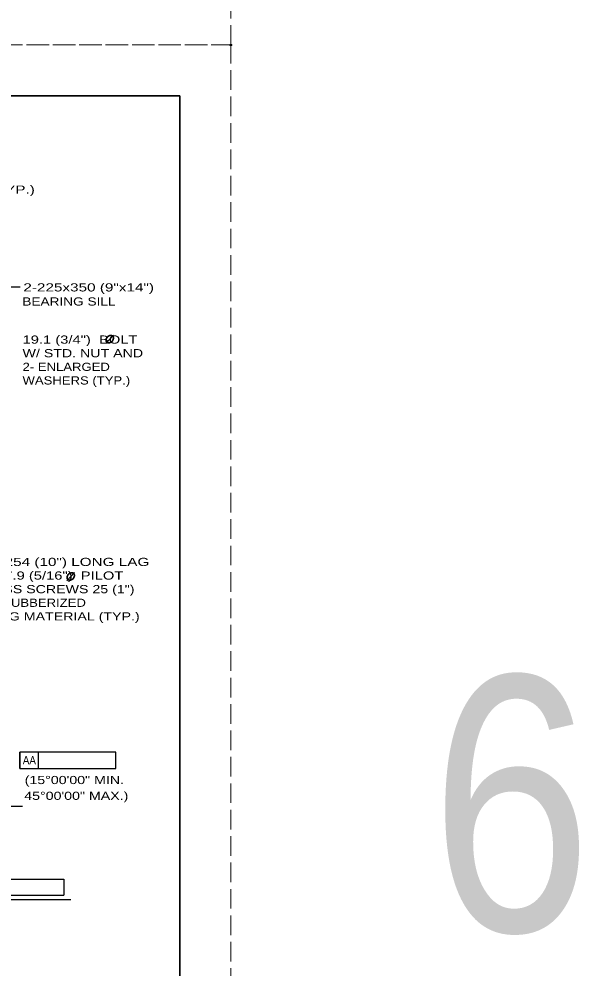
# Model space of a CAD drawing. Extents: x -6.4 to 73.1, y -66 to 0.
# Drawn here: x 64.89 to 73.12, y -57.56 to -43.62 of the extents above; entities that cross this region are included whole.
import ezdxf
from ezdxf.enums import TextEntityAlignment as Align

# ---------------------------------------------------------------- set-up
doc = ezdxf.new("R2010")
doc.units = 0
doc.header["$LTSCALE"] = 0.048
doc.header["$PDMODE"] = 32
doc.header["$PDSIZE"] = 0.024
doc.linetypes.add('LONG_DASHED', pattern=[7.5, 6, -1.5])
for name, color, linetype, lineweight in [('1', 7, 'Continuous', 13), ('4', 7, 'Continuous', 25), ('5', 7, 'Continuous', 25), ('63', 7, 'LONG_DASHED', 13)]:
    doc.layers.add(name, color=color, linetype=linetype, lineweight=lineweight)
doc.layers.add('53', color=7, linetype='Continuous')
doc.layers.add('62', color=7, linetype='Continuous')

msp = doc.modelspace()

# ---------------------------------------------------------------- linework, layer by layer
at = {"layer": '1', "lineweight": 35}
msp.add_lwpolyline([(35.75, -65.25), (67.25, -65.25), (67.25, -44.75), (35.75, -44.75)], close=True, dxfattribs=at)
at = {"layer": '4'}
for p, q in [((64.73475, -47.55442), (64.9015, -47.55442)), ((64.89708, -54.391), (64.89708, -54.62717)), ((66.30908, -54.391), (64.89708, -54.391)), ((64.89708, -54.62717), (64.89708, -54.391)), ((65.17092, -54.62717), (65.17092, -54.391)), ((66.30908, -54.62717), (66.30908, -54.391)), ((64.89708, -54.62717), (66.30908, -54.62717)), ((63.36142, -55.18092), (64.94, -55.18092)), ((63.97042, -56.25308), (65.54517, -56.25317)), ((65.54517, -56.25317), (65.54517, -56.48933)), ((63.45308, -56.55433), (65.65033, -56.55433))]:
    msp.add_line(p, q, dxfattribs=at)
msp.add_lwpolyline([(63.97042, -56.25308), (63.97042, -56.48933), (65.54517, -56.48933)], dxfattribs=at)
at = {"layer": '5', "lineweight": 35}
for p, q in [((66.16342, -48.3885), (66.27542, -48.26592)), ((65.59017, -51.87458), (65.70217, -51.752))]:
    msp.add_line(p, q, dxfattribs=at)
for points in [[(66.26375, -48.278), (66.255, -48.27117), (66.24625, -48.26875), (66.23525, -48.26775), (66.229, -48.26775), (66.21825, -48.27025), (66.20842, -48.27475), (66.2015, -48.27867), (66.18825, -48.28925), (66.17792, -48.30275), (66.17167, -48.31542), (66.168, -48.327), (66.16692, -48.33775), (66.168, -48.347), (66.1725, -48.36017), (66.17725, -48.367), (66.18692, -48.37425), (66.20142, -48.37775), (66.21792, -48.37725), (66.23875, -48.36775), (66.254, -48.35467), (66.2655, -48.33875), (66.273, -48.32217), (66.2755, -48.30375), (66.27225, -48.29192), (66.26425, -48.278)], [(65.6905, -51.76408), (65.68175, -51.75725), (65.673, -51.75483), (65.662, -51.75383), (65.65575, -51.75383), (65.645, -51.75633), (65.63517, -51.76083), (65.62825, -51.76475), (65.615, -51.77533), (65.60467, -51.78883), (65.59842, -51.8015), (65.59475, -51.81308), (65.59367, -51.82383), (65.59475, -51.83308), (65.59925, -51.84625), (65.604, -51.85308), (65.61367, -51.86033), (65.62817, -51.86383), (65.64467, -51.86333), (65.6655, -51.85383), (65.68075, -51.84075), (65.69225, -51.82483), (65.69975, -51.80825), (65.70225, -51.78983), (65.699, -51.778), (65.691, -51.76408)]]:
    msp.add_spline(points, degree=3, dxfattribs=at)
at = {"layer": '62'}
msp.add_point((68, -44), dxfattribs=at)
at = {"layer": '63'}
for points in [[(34, -44), (68, -44), (68, -22), (34, -22)], [(34, -66), (68, -66), (68, -44), (34, -44)]]:
    msp.add_lwpolyline(points, close=True, dxfattribs=at)

# ---------------------------------------------------------------- texts
at = {"layer": '4', "width": 1.4}
msp.add_text('12.7 (1/2")  BOLT W/ STD. NUT & WASHERS (TYP.)', height=0.12, dxfattribs=at).set_placement((59.809, -46.18533))
at = {"layer": '4', "width": 0.9}
msp.add_text('AA', height=0.12, dxfattribs=at).set_placement((65.03846, -54.56767), align=Align.CENTER)
at = {"layer": '5'}
for s, width, p in [('2-225x350 (9"x14")', 1.4, (64.95033, -47.62158)), ('BEARING SILL', 1.25, (64.93458, -47.82908)), ('19.1 (3/4")  BOLT', 1.35, (64.93817, -48.38858)), ('W/ STD. NUT AND', 1.3, (64.93817, -48.58858)), ('2- ENLARGED', 1.2, (64.93817, -48.78858)), ('WASHERS (TYP.)', 1.2, (64.93817, -48.98858)), ('12.7 (1/2")  x 254 (10") LONG LAG', 1.4, (63.33408, -51.65475)), ('SCREWS W/ 7.9 (5/16")  PILOT', 1.35, (63.33408, -51.85475)), ('HOLE.  RECESS SCREWS 25 (1")', 1.3, (63.33408, -52.05475)), ('AND SEAL W/ RUBBERIZED', 1.2, (63.33408, -52.25475)), ('JOINT SEALING MATERIAL (TYP.)', 1.3, (63.33408, -52.45475))]:
    msp.add_text(s, height=0.12, dxfattribs=dict(at, width=width)).set_placement(p)
at = {"layer": '5', "width": 1.3}
for s, p in [('(15°00\'00" MIN.', (65.69987, -54.8585)), ('45°00\'00" MAX.)', (65.72862, -55.09058))]:
    msp.add_text(s, height=0.12, dxfattribs=at).set_placement(p, align=Align.CENTER)
at = {"layer": '53', "width": 0.85}
msp.add_text('6', height=3.75, dxfattribs=at).set_placement((72.12262, -57.02175), align=Align.CENTER)

doc.saveas('drawing.dxf')
